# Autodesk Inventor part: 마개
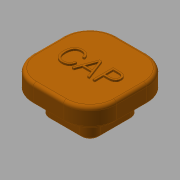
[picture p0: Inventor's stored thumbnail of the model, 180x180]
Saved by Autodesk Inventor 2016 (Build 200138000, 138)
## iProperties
Created: 2018-03
Part Number: 마개
Material: 고무
Document SubType Name: Modeling
Designer: mduedu
Density: 1 g/cm^3
Appearance: 주황색
Author: mduedu
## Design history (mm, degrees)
sketch "스케치1"
  geometry: L1 (12.5, 12.5)-(-12.5, 12.5); L2 (-12.5, 12.5)-(-12.5, -12.5); L3 (-12.5, -12.5)-(12.5, -12.5); L4 (12.5, -12.5)-(12.5, 12.5); L5 (12.5, 12.5)-(-12.5, -12.5); L6 (-12.5, 12.5)-(12.5, -12.5); 1 further point
  constraints: 12 end point, 2 midpoint, 2 parallel, 1 horizontal, 1 perpendicular
  dimensions: "d0" = 25 distance of L3.end L2.end; "d1" = 25 distance of L2.end L1.end
extrude "돌출1" new body sketch "스케치1" distance "d2" = 6; taper "d3" = 0 deg
fillet "모깎기1" dims "d4" = 8
fillet "모깎기2" dims "d5" = 1
sketch "스케치2"
  geometry: L1 (4.5, -12.5)-(-4.5, -12.5) reference; L2 (12.5, 4.5)-(12.5, -4.5) reference; L3 (-4.5, 12.5)-(4.5, 12.5) reference; L4 (-12.5, -4.5)-(-12.5, 4.5) reference; L5 (7.5, 4.5)-(7.5, -4.5); L6 (4.5, -7.5)-(-4.5, -7.5); L7 (-7.5, -4.5)-(-7.5, 4.5); L8 (-4.5, 7.5)-(4.5, 7.5); A1 r 8 centre (-4.5, -4.5) between (-12.5, -4.5) and (-4.5, -12.5) reference; A2 r 8 centre (4.5, -4.5) between (4.5, -12.5) and (12.5, -4.5) reference; A3 r 8 centre (4.5, 4.5) between (12.5, 4.5) and (4.5, 12.5) reference; A4 r 8 centre (-4.5, 4.5) between (-4.5, 12.5) and (-12.5, 4.5) reference; A5 r 3 centre (4.5, 4.5) between (7.5, 4.5) and (4.5, 7.5); A6 r 3 centre (4.5, -4.5) between (4.5, -7.5) and (7.5, -4.5); A7 r 3 centre (-4.5, -4.5) between (-7.5, -4.5) and (-4.5, -7.5); A8 r 3 centre (-4.5, 4.5) between (-4.5, 7.5) and (-7.5, 4.5); 1 further point
  constraints: 8 end point, 8 point on circle, 4 centre point, 7 other
  dimensions: "d6" = 5 distance between parallel lines of L8 L3
extrude "돌출2" join sketch "스케치2" distance "d7" = 6; taper "d8" = 0 deg
sketch "스케치3"
  geometry: L1 (4.5, 7.5)-(-4.5, 7.5) reference; L2 (-7.5, 4.5)-(-7.5, -4.5) reference; L3 (-4.5, -7.5)-(4.5, -7.5) reference; L4 (7.5, -4.5)-(7.5, 4.5) reference; L5 (-4.5, 5)-(4.5, 5); L6 (5, 4.5)-(5, -4.5); L7 (4.5, -5)-(-4.5, -5); L8 (-5, -4.5)-(-5, 4.5); A1 r 3 centre (4.5, 4.5) between (7.5, 4.5) and (4.5, 7.5) reference; A2 r 3 centre (-4.5, 4.5) between (-4.5, 7.5) and (-7.5, 4.5) reference; A3 r 3 centre (-4.5, -4.5) between (-7.5, -4.5) and (-4.5, -7.5) reference; A4 r 3 centre (4.5, -4.5) between (4.5, -7.5) and (7.5, -4.5) reference; A5 r 0.5 centre (4.5, 4.5) between (5, 4.5) and (4.5, 5); A6 r 0.5 centre (4.5, -4.5) between (4.5, -5) and (5, -4.5); A7 r 0.5 centre (-4.5, -4.5) between (-5, -4.5) and (-4.5, -5); A8 r 0.5 centre (-4.5, 4.5) between (-4.5, 5) and (-5, 4.5); 1 further point
  constraints: 8 end point, 8 point on circle, 4 centre point, 7 other
  dimensions: "d9" = 2.5 distance between parallel lines of L5 L1
extrude "돌출3" cut sketch "스케치3" stored distance "d10" = 10; taper "d11" = 0 deg
fillet "모깎기3" dims "d12" = 1
sketch "스케치4"
  geometry: L1 (7.5, 4.5)-(7.5, -4.5) reference; L2 (4.5, -7.5)-(-4.5, -7.5) reference; L3 (-7.5, -4.5)-(-7.5, 4.5) reference; L4 (-4.5, 7.5)-(4.5, 7.5) reference; L5 (4.5, -12.5)-(-4.5, -12.5) reference; L6 (12.5, 4.5)-(12.5, -4.5) reference; L7 (-4.5, 12.5)-(4.5, 12.5) reference; L8 (-12.5, -4.5)-(-12.5, 4.5) reference; L9 (11.5, 4.5)-(11.5, -4.5); L10 (4.5, -11.5)-(-4.5, -11.5); L11 (-11.5, -4.5)-(-11.5, 4.5); L12 (-4.5, 11.5)-(4.5, 11.5); A1 r 3 centre (4.5, -4.5) between (4.5, -7.5) and (7.5, -4.5) reference; A2 r 3 centre (-4.5, -4.5) between (-7.5, -4.5) and (-4.5, -7.5) reference; A3 r 3 centre (-4.5, 4.5) between (-4.5, 7.5) and (-7.5, 4.5) reference; A4 r 3 centre (4.5, 4.5) between (7.5, 4.5) and (4.5, 7.5) reference; A5 r 8 centre (-4.5, -4.5) between (-12.5, -4.5) and (-4.5, -12.5) reference; A6 r 8 centre (4.5, -4.5) between (4.5, -12.5) and (12.5, -4.5) reference; A7 r 8 centre (4.5, 4.5) between (12.5, 4.5) and (4.5, 12.5) reference; A8 r 8 centre (-4.5, 4.5) between (-4.5, 12.5) and (-12.5, 4.5) reference; A9 r 7 centre (4.5, 4.5) between (11.5, 4.5) and (4.5, 11.5); A10 r 7 centre (4.5, -4.5) between (4.5, -11.5) and (11.5, -4.5); A11 r 7 centre (-4.5, -4.5) between (-11.5, -4.5) and (-4.5, -11.5); A12 r 7 centre (-4.5, 4.5) between (-4.5, 11.5) and (-11.5, 4.5); 1 further point
  constraints: 8 end point, 8 point on circle, 4 centre point, 7 other
  dimensions: "d13" = 1 distance between parallel lines of L12 L7
extrude "돌출4" cut sketch "스케치4" distance "d14" = 1; taper "d15" = 0 deg
chamfer "모따기1" distance "d16" = 0.5; stored, may be unused: second distance "d17" = 2, angle "d18" = 45 deg
sketch "스케치5"
  geometry: 2 further points
  constraints: 1 coincident, 1 other
feature "엠보싱1" sketch "스케치5" dims "d0" = 25, "d1" = 25, "d19" = 0.5, "d20" = 0
node "솔리드1"
node "투영된 루프1"
node "투영된 루프2"
node "투영된 루프3"
